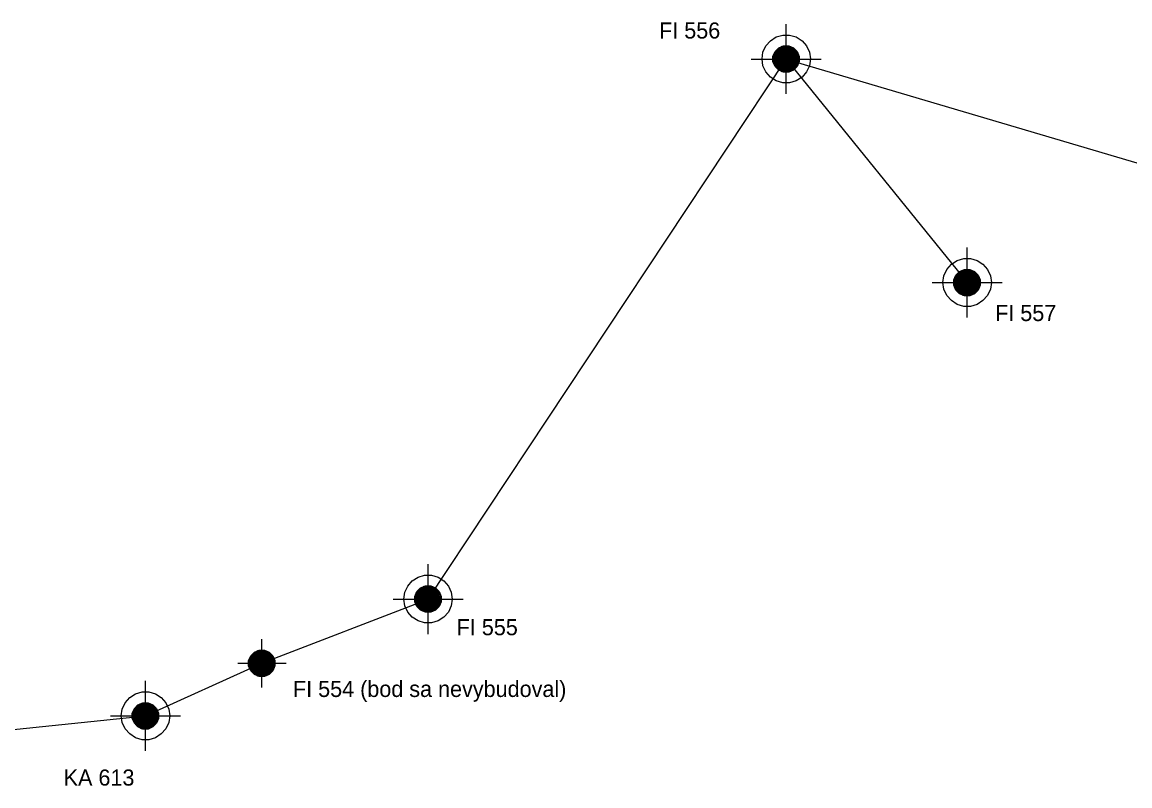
# Model space of a CAD drawing. Extents: x -346533 to -339969, y -1273090 to -1271585.
# Drawn here: x -340999 to -340484, y -1271944 to -1271589 of the extents above; entities that cross this region are included whole.
import ezdxf

# ---------------------------------------------------------------- set-up
doc = ezdxf.new("R2010")
doc.units = 0
for name, color, linetype in [('BP_11', 7, 'Continuous'), ('BP_12', 7, 'Continuous'), ('BP_14', 7, 'Continuous')]:
    doc.layers.add(name, color=color, linetype=linetype)

msp = doc.modelspace()

# ---------------------------------------------------------------- linework, layer by layer
at = {"layer": 'BP_11'}
for points in [[(-340643.57, -1271622.32), (-340643.57, -1271615.97), (-340643.57, -1271609.62), (-340643.57, -1271603.27), (-340643.57, -1271596.92), (-340643.57, -1271590.57), (-340643.57, -1271589.82)], [(-340643.57, -1271599.92), (-340642.37, -1271599.92), (-340640.12, -1271600.87), (-340638.42, -1271602.57), (-340637.47, -1271604.82), (-340637.47, -1271607.27), (-340638.42, -1271609.52), (-340640.12, -1271611.22), (-340642.37, -1271612.17), (-340644.82, -1271612.17), (-340647.07, -1271611.22), (-340648.77, -1271609.52), (-340649.72, -1271607.27), (-340649.72, -1271604.82), (-340648.77, -1271602.57), (-340647.07, -1271600.87), (-340644.82, -1271599.92), (-340643.62, -1271599.92), (-340641.82, -1271600.27), (-340645.42, -1271600.27), (-340646.22, -1271600.67), (-340641.02, -1271600.67), (-340640.22, -1271601.07), (-340646.57, -1271601.07), (-340647.02, -1271601.07), (-340647.42, -1271601.47), (-340641.07, -1271601.47), (-340639.82, -1271601.47), (-340639.42, -1271601.87), (-340645.77, -1271601.87), (-340647.82, -1271601.87), (-340648.22, -1271602.27), (-340641.87, -1271602.27), (-340639.02, -1271602.27), (-340638.62, -1271602.67), (-340644.97, -1271602.67), (-340648.62, -1271602.67), (-340648.62, -1271603.07), (-340642.27, -1271603.07), (-340638.62, -1271603.07), (-340638.22, -1271603.47), (-340644.57, -1271603.47), (-340649.02, -1271603.47), (-340649.02, -1271603.87), (-340642.67, -1271603.87), (-340638.22, -1271603.87), (-340638.22, -1271604.27), (-340644.57, -1271604.27), (-340649.02, -1271604.27), (-340649.42, -1271604.67), (-340643.07, -1271604.67), (-340637.82, -1271604.67), (-340637.82, -1271605.07), (-340644.17, -1271605.07), (-340649.42, -1271605.07), (-340649.42, -1271605.47), (-340643.07, -1271605.47), (-340637.82, -1271605.47), (-340637.82, -1271605.87), (-340644.17, -1271605.87), (-340649.42, -1271605.87), (-340649.42, -1271606.27), (-340643.07, -1271606.27), (-340637.82, -1271606.27), (-340637.82, -1271606.67), (-340644.17, -1271606.67), (-340649.42, -1271606.67), (-340649.42, -1271607.07), (-340643.07, -1271607.07), (-340637.82, -1271607.07), (-340637.82, -1271607.47), (-340644.17, -1271607.47), (-340649.42, -1271607.47), (-340649.42, -1271607.87), (-340643.07, -1271607.87), (-340637.82, -1271607.87), (-340638.22, -1271608.27), (-340644.57, -1271608.27), (-340649.02, -1271608.27), (-340649.02, -1271608.67), (-340642.67, -1271608.67), (-340638.22, -1271608.67), (-340638.62, -1271609.07), (-340644.97, -1271609.07), (-340648.62, -1271609.07), (-340648.62, -1271609.47), (-340642.27, -1271609.47), (-340638.62, -1271609.47), (-340639.02, -1271609.87), (-340645.37, -1271609.87), (-340648.22, -1271609.87), (-340647.82, -1271610.27), (-340641.47, -1271610.27), (-340639.42, -1271610.27), (-340639.82, -1271610.67), (-340646.17, -1271610.67), (-340647.42, -1271610.67), (-340647.02, -1271611.07), (-340640.67, -1271611.07), (-340640.22, -1271611.07)], [(-340659.82, -1271606.07), (-340653.47, -1271606.07), (-340647.12, -1271606.07), (-340640.77, -1271606.07), (-340634.42, -1271606.07), (-340628.07, -1271606.07), (-340627.32, -1271606.07)], [(-340640.22, -1271611.07), (-340641.02, -1271611.47), (-340646.22, -1271611.47), (-340645.42, -1271611.87), (-340641.82, -1271611.87)], [(-340559.43, -1271726.28), (-340559.43, -1271719.93), (-340559.43, -1271713.58), (-340559.43, -1271707.23), (-340559.43, -1271700.88), (-340559.43, -1271694.53), (-340559.43, -1271693.78)], [(-340559.43, -1271703.88), (-340558.23, -1271703.88), (-340555.98, -1271704.83), (-340554.28, -1271706.53), (-340553.33, -1271708.78), (-340553.33, -1271711.23), (-340554.28, -1271713.48), (-340555.98, -1271715.18), (-340558.23, -1271716.13), (-340560.68, -1271716.13), (-340562.93, -1271715.18), (-340564.63, -1271713.48), (-340565.58, -1271711.23), (-340565.58, -1271708.78), (-340564.63, -1271706.53), (-340562.93, -1271704.83), (-340560.68, -1271703.88), (-340559.48, -1271703.88), (-340557.68, -1271704.23), (-340561.28, -1271704.23), (-340562.08, -1271704.63), (-340556.88, -1271704.63), (-340556.08, -1271705.03), (-340562.43, -1271705.03), (-340562.88, -1271705.03), (-340563.28, -1271705.43), (-340556.93, -1271705.43), (-340555.68, -1271705.43), (-340555.28, -1271705.83), (-340561.63, -1271705.83), (-340563.68, -1271705.83), (-340564.08, -1271706.23), (-340557.73, -1271706.23), (-340554.88, -1271706.23), (-340554.48, -1271706.63), (-340560.83, -1271706.63), (-340564.48, -1271706.63), (-340564.48, -1271707.03), (-340558.13, -1271707.03), (-340554.48, -1271707.03), (-340554.08, -1271707.43), (-340560.43, -1271707.43), (-340564.88, -1271707.43), (-340564.88, -1271707.83), (-340558.53, -1271707.83), (-340554.08, -1271707.83), (-340554.08, -1271708.23), (-340560.43, -1271708.23), (-340564.88, -1271708.23), (-340565.28, -1271708.63), (-340558.93, -1271708.63), (-340553.68, -1271708.63), (-340553.68, -1271709.03), (-340560.03, -1271709.03), (-340565.28, -1271709.03), (-340565.28, -1271709.43), (-340558.93, -1271709.43), (-340553.68, -1271709.43), (-340553.68, -1271709.83), (-340560.03, -1271709.83), (-340565.28, -1271709.83), (-340565.28, -1271710.23), (-340558.93, -1271710.23), (-340553.68, -1271710.23), (-340553.68, -1271710.63), (-340560.03, -1271710.63), (-340565.28, -1271710.63), (-340565.28, -1271711.03), (-340558.93, -1271711.03), (-340553.68, -1271711.03), (-340553.68, -1271711.43), (-340560.03, -1271711.43), (-340565.28, -1271711.43), (-340565.28, -1271711.83), (-340558.93, -1271711.83), (-340553.68, -1271711.83), (-340554.08, -1271712.23), (-340560.43, -1271712.23), (-340564.88, -1271712.23), (-340564.88, -1271712.63), (-340558.53, -1271712.63), (-340554.08, -1271712.63), (-340554.48, -1271713.03), (-340560.83, -1271713.03), (-340564.48, -1271713.03), (-340564.48, -1271713.43), (-340558.13, -1271713.43), (-340554.48, -1271713.43), (-340554.88, -1271713.83), (-340561.23, -1271713.83), (-340564.08, -1271713.83), (-340563.68, -1271714.23), (-340557.33, -1271714.23), (-340555.28, -1271714.23), (-340555.68, -1271714.63), (-340562.03, -1271714.63), (-340563.28, -1271714.63), (-340562.88, -1271715.03), (-340556.53, -1271715.03), (-340556.08, -1271715.03)], [(-340575.68, -1271710.03), (-340569.33, -1271710.03), (-340562.98, -1271710.03), (-340556.63, -1271710.03), (-340550.28, -1271710.03), (-340543.93, -1271710.03), (-340543.18, -1271710.03)], [(-340556.08, -1271715.03), (-340556.88, -1271715.43), (-340562.08, -1271715.43), (-340561.28, -1271715.83), (-340557.68, -1271715.83)], [(-340810.08, -1271873.47), (-340810.08, -1271867.12), (-340810.08, -1271860.77), (-340810.08, -1271854.42), (-340810.08, -1271848.07), (-340810.08, -1271841.72), (-340810.08, -1271840.97)], [(-340810.08, -1271851.07), (-340808.88, -1271851.07), (-340806.63, -1271852.02), (-340804.93, -1271853.72), (-340803.98, -1271855.97), (-340803.98, -1271858.42), (-340804.93, -1271860.67), (-340806.63, -1271862.37), (-340808.88, -1271863.32), (-340811.33, -1271863.32), (-340813.58, -1271862.37), (-340815.28, -1271860.67), (-340816.23, -1271858.42), (-340816.23, -1271855.97), (-340815.28, -1271853.72), (-340813.58, -1271852.02), (-340811.33, -1271851.07), (-340810.13, -1271851.07), (-340808.33, -1271851.42), (-340811.93, -1271851.42), (-340812.73, -1271851.82), (-340807.53, -1271851.82), (-340806.73, -1271852.22), (-340813.08, -1271852.22), (-340813.53, -1271852.22), (-340813.93, -1271852.62), (-340807.58, -1271852.62), (-340806.33, -1271852.62), (-340805.93, -1271853.02), (-340812.28, -1271853.02), (-340814.33, -1271853.02), (-340814.73, -1271853.42), (-340808.38, -1271853.42), (-340805.53, -1271853.42), (-340805.13, -1271853.82), (-340811.48, -1271853.82), (-340815.13, -1271853.82), (-340815.13, -1271854.22), (-340808.78, -1271854.22), (-340805.13, -1271854.22), (-340804.73, -1271854.62), (-340811.08, -1271854.62), (-340815.53, -1271854.62), (-340815.53, -1271855.02), (-340809.18, -1271855.02), (-340804.73, -1271855.02), (-340804.73, -1271855.42), (-340811.08, -1271855.42), (-340815.53, -1271855.42), (-340815.93, -1271855.82), (-340809.58, -1271855.82), (-340804.33, -1271855.82), (-340804.33, -1271856.22), (-340810.68, -1271856.22), (-340815.93, -1271856.22), (-340815.93, -1271856.62), (-340809.58, -1271856.62), (-340804.33, -1271856.62), (-340804.33, -1271857.02), (-340810.68, -1271857.02), (-340815.93, -1271857.02), (-340815.93, -1271857.42), (-340809.58, -1271857.42), (-340804.33, -1271857.42), (-340804.33, -1271857.82), (-340810.68, -1271857.82), (-340815.93, -1271857.82), (-340815.93, -1271858.22), (-340809.58, -1271858.22), (-340804.33, -1271858.22), (-340804.33, -1271858.62), (-340810.68, -1271858.62), (-340815.93, -1271858.62), (-340815.93, -1271859.02), (-340809.58, -1271859.02), (-340804.33, -1271859.02), (-340804.73, -1271859.42), (-340811.08, -1271859.42), (-340815.53, -1271859.42), (-340815.53, -1271859.82), (-340809.18, -1271859.82), (-340804.73, -1271859.82), (-340805.13, -1271860.22), (-340811.48, -1271860.22), (-340815.13, -1271860.22), (-340815.13, -1271860.62), (-340808.78, -1271860.62), (-340805.13, -1271860.62), (-340805.53, -1271861.02), (-340811.88, -1271861.02), (-340814.73, -1271861.02), (-340814.33, -1271861.42), (-340807.98, -1271861.42), (-340805.93, -1271861.42), (-340806.33, -1271861.82), (-340812.68, -1271861.82), (-340813.93, -1271861.82), (-340813.53, -1271862.22), (-340807.18, -1271862.22), (-340806.73, -1271862.22)], [(-340826.33, -1271857.22), (-340819.98, -1271857.22), (-340813.63, -1271857.22), (-340807.28, -1271857.22), (-340800.93, -1271857.22), (-340794.58, -1271857.22), (-340793.83, -1271857.22)], [(-340806.73, -1271862.22), (-340807.53, -1271862.62), (-340812.73, -1271862.62), (-340811.93, -1271863.02), (-340808.33, -1271863.02)], [(-340887.37, -1271898.31), (-340887.37, -1271891.96), (-340887.37, -1271885.61), (-340887.37, -1271879.26), (-340887.37, -1271875.81)], [(-340887.37, -1271880.91), (-340886.17, -1271880.91), (-340883.92, -1271881.86), (-340882.22, -1271883.56), (-340881.27, -1271885.81), (-340881.27, -1271888.26), (-340882.22, -1271890.51), (-340883.92, -1271892.21), (-340886.17, -1271893.16), (-340888.62, -1271893.16), (-340890.87, -1271892.21), (-340892.57, -1271890.51), (-340893.52, -1271888.26), (-340893.52, -1271885.81), (-340892.57, -1271883.56), (-340890.87, -1271881.86), (-340888.62, -1271880.91), (-340887.42, -1271880.91), (-340885.62, -1271881.26), (-340889.22, -1271881.26), (-340890.02, -1271881.66), (-340884.82, -1271881.66), (-340884.02, -1271882.06), (-340890.37, -1271882.06), (-340890.82, -1271882.06), (-340891.22, -1271882.46), (-340884.87, -1271882.46), (-340883.62, -1271882.46), (-340883.22, -1271882.86), (-340889.57, -1271882.86), (-340891.62, -1271882.86), (-340892.02, -1271883.26), (-340885.67, -1271883.26), (-340882.82, -1271883.26), (-340882.42, -1271883.66), (-340888.77, -1271883.66), (-340892.42, -1271883.66), (-340892.42, -1271884.06), (-340886.07, -1271884.06), (-340882.42, -1271884.06), (-340882.02, -1271884.46), (-340888.37, -1271884.46), (-340892.82, -1271884.46), (-340892.82, -1271884.86), (-340886.47, -1271884.86), (-340882.02, -1271884.86), (-340881.62, -1271885.26), (-340887.97, -1271885.26), (-340893.22, -1271885.26), (-340893.22, -1271885.66), (-340886.87, -1271885.66), (-340881.62, -1271885.66), (-340881.62, -1271886.06), (-340887.97, -1271886.06), (-340893.22, -1271886.06), (-340893.22, -1271886.46), (-340886.87, -1271886.46), (-340881.62, -1271886.46), (-340881.62, -1271886.86), (-340887.97, -1271886.86), (-340893.22, -1271886.86), (-340893.22, -1271887.26), (-340886.87, -1271887.26), (-340881.62, -1271887.26), (-340881.62, -1271887.66), (-340887.97, -1271887.66), (-340893.22, -1271887.66), (-340893.22, -1271888.06), (-340886.87, -1271888.06), (-340881.62, -1271888.06), (-340881.62, -1271888.46), (-340887.97, -1271888.46), (-340893.22, -1271888.46), (-340893.22, -1271888.86), (-340886.87, -1271888.86), (-340881.62, -1271888.86), (-340882.02, -1271889.26), (-340888.37, -1271889.26), (-340892.82, -1271889.26), (-340892.82, -1271889.66), (-340886.47, -1271889.66), (-340882.02, -1271889.66), (-340882.42, -1271890.06), (-340888.77, -1271890.06), (-340892.42, -1271890.06), (-340892.42, -1271890.46), (-340886.07, -1271890.46), (-340882.42, -1271890.46), (-340882.82, -1271890.86), (-340889.17, -1271890.86), (-340892.02, -1271890.86), (-340891.62, -1271891.26), (-340885.27, -1271891.26), (-340883.22, -1271891.26), (-340883.62, -1271891.66), (-340889.97, -1271891.66), (-340891.22, -1271891.66), (-340890.82, -1271892.06), (-340884.47, -1271892.06), (-340884.02, -1271892.06)], [(-340898.62, -1271887.06), (-340892.27, -1271887.06), (-340885.92, -1271887.06), (-340879.57, -1271887.06), (-340876.12, -1271887.06)], [(-340941.47, -1271927.77), (-340941.47, -1271921.42), (-340941.47, -1271915.07), (-340941.47, -1271908.72), (-340941.47, -1271902.37), (-340941.47, -1271896.02), (-340941.47, -1271895.27)], [(-340884.02, -1271892.06), (-340884.82, -1271892.46), (-340890.02, -1271892.46), (-340889.22, -1271892.86), (-340885.62, -1271892.86)], [(-340941.47, -1271905.37), (-340940.27, -1271905.37), (-340938.02, -1271906.32), (-340936.32, -1271908.02), (-340935.37, -1271910.27), (-340935.37, -1271912.72), (-340936.32, -1271914.97), (-340938.02, -1271916.67), (-340940.27, -1271917.62), (-340942.72, -1271917.62), (-340944.97, -1271916.67), (-340946.67, -1271914.97), (-340947.62, -1271912.72), (-340947.62, -1271910.27), (-340946.67, -1271908.02), (-340944.97, -1271906.32), (-340942.72, -1271905.37), (-340941.52, -1271905.37), (-340939.72, -1271905.72), (-340943.32, -1271905.72), (-340944.12, -1271906.12), (-340938.92, -1271906.12), (-340938.12, -1271906.52), (-340944.47, -1271906.52), (-340944.92, -1271906.52), (-340945.32, -1271906.92), (-340938.97, -1271906.92), (-340937.72, -1271906.92), (-340937.32, -1271907.32), (-340943.67, -1271907.32), (-340945.72, -1271907.32), (-340946.12, -1271907.72), (-340939.77, -1271907.72), (-340936.92, -1271907.72), (-340936.52, -1271908.12), (-340942.87, -1271908.12), (-340946.52, -1271908.12), (-340946.52, -1271908.52), (-340940.17, -1271908.52), (-340936.52, -1271908.52), (-340936.12, -1271908.92), (-340942.47, -1271908.92), (-340946.92, -1271908.92), (-340946.92, -1271909.32), (-340940.57, -1271909.32), (-340936.12, -1271909.32), (-340936.12, -1271909.72), (-340942.47, -1271909.72), (-340946.92, -1271909.72), (-340947.32, -1271910.12), (-340940.97, -1271910.12), (-340935.72, -1271910.12), (-340935.72, -1271910.52), (-340942.07, -1271910.52), (-340947.32, -1271910.52), (-340947.32, -1271910.92), (-340940.97, -1271910.92), (-340935.72, -1271910.92), (-340935.72, -1271911.32), (-340942.07, -1271911.32), (-340947.32, -1271911.32), (-340947.32, -1271911.72), (-340940.97, -1271911.72), (-340935.72, -1271911.72), (-340935.72, -1271912.12), (-340942.07, -1271912.12), (-340947.32, -1271912.12), (-340947.32, -1271912.52), (-340940.97, -1271912.52), (-340935.72, -1271912.52), (-340935.72, -1271912.92), (-340942.07, -1271912.92), (-340947.32, -1271912.92), (-340947.32, -1271913.32), (-340940.97, -1271913.32), (-340935.72, -1271913.32), (-340936.12, -1271913.72), (-340942.47, -1271913.72), (-340946.92, -1271913.72), (-340946.92, -1271914.12), (-340940.57, -1271914.12), (-340936.12, -1271914.12), (-340936.52, -1271914.52), (-340942.87, -1271914.52), (-340946.52, -1271914.52), (-340946.52, -1271914.92), (-340940.17, -1271914.92), (-340936.52, -1271914.92), (-340936.92, -1271915.32), (-340943.27, -1271915.32), (-340946.12, -1271915.32), (-340945.72, -1271915.72), (-340939.37, -1271915.72), (-340937.32, -1271915.72), (-340937.72, -1271916.12), (-340944.07, -1271916.12), (-340945.32, -1271916.12), (-340944.92, -1271916.52), (-340938.57, -1271916.52), (-340938.12, -1271916.52)], [(-340957.72, -1271911.52), (-340951.37, -1271911.52), (-340945.02, -1271911.52), (-340938.67, -1271911.52), (-340932.32, -1271911.52), (-340925.97, -1271911.52), (-340925.22, -1271911.52)], [(-340938.12, -1271916.52), (-340938.92, -1271916.92), (-340944.12, -1271916.92), (-340943.32, -1271917.32), (-340939.72, -1271917.32)]]:
    msp.add_lwpolyline(points, dxfattribs=at)
for points in [[(-340641.97, -1271594.92), (-340638.92, -1271595.82), (-340636.22, -1271597.57), (-340634.12, -1271599.97), (-340632.77, -1271602.87), (-340632.32, -1271606.02), (-340632.77, -1271609.17), (-340634.12, -1271612.07), (-340636.22, -1271614.47), (-340638.92, -1271616.22), (-340641.97, -1271617.12), (-340645.17, -1271617.12), (-340648.22, -1271616.22), (-340650.92, -1271614.47), (-340653.02, -1271612.07), (-340654.37, -1271609.17), (-340654.82, -1271606.02), (-340654.37, -1271602.87), (-340653.02, -1271599.97), (-340650.92, -1271597.57), (-340648.22, -1271595.82), (-340645.17, -1271594.92)], [(-340557.83, -1271698.88), (-340554.78, -1271699.78), (-340552.08, -1271701.53), (-340549.98, -1271703.93), (-340548.63, -1271706.83), (-340548.18, -1271709.98), (-340548.63, -1271713.13), (-340549.98, -1271716.03), (-340552.08, -1271718.43), (-340554.78, -1271720.18), (-340557.83, -1271721.08), (-340561.03, -1271721.08), (-340564.08, -1271720.18), (-340566.78, -1271718.43), (-340568.88, -1271716.03), (-340570.23, -1271713.13), (-340570.68, -1271709.98), (-340570.23, -1271706.83), (-340568.88, -1271703.93), (-340566.78, -1271701.53), (-340564.08, -1271699.78), (-340561.03, -1271698.88)], [(-340808.48, -1271846.07), (-340805.43, -1271846.97), (-340802.73, -1271848.72), (-340800.63, -1271851.12), (-340799.28, -1271854.02), (-340798.83, -1271857.17), (-340799.28, -1271860.32), (-340800.63, -1271863.22), (-340802.73, -1271865.62), (-340805.43, -1271867.37), (-340808.48, -1271868.27), (-340811.68, -1271868.27), (-340814.73, -1271867.37), (-340817.43, -1271865.62), (-340819.53, -1271863.22), (-340820.88, -1271860.32), (-340821.33, -1271857.17), (-340820.88, -1271854.02), (-340819.53, -1271851.12), (-340817.43, -1271848.72), (-340814.73, -1271846.97), (-340811.68, -1271846.07)], [(-340886.17, -1271880.91), (-340883.92, -1271881.86), (-340882.22, -1271883.56), (-340881.27, -1271885.81), (-340881.27, -1271888.26), (-340882.22, -1271890.51), (-340883.92, -1271892.21), (-340886.17, -1271893.16), (-340888.62, -1271893.16), (-340890.87, -1271892.21), (-340892.57, -1271890.51), (-340893.52, -1271888.26), (-340893.52, -1271885.81), (-340892.57, -1271883.56), (-340890.87, -1271881.86), (-340888.62, -1271880.91)], [(-340939.87, -1271900.37), (-340936.82, -1271901.27), (-340934.12, -1271903.02), (-340932.02, -1271905.42), (-340930.67, -1271908.32), (-340930.22, -1271911.47), (-340930.67, -1271914.62), (-340932.02, -1271917.52), (-340934.12, -1271919.92), (-340936.82, -1271921.67), (-340939.87, -1271922.57), (-340943.07, -1271922.57), (-340946.12, -1271921.67), (-340948.82, -1271919.92), (-340950.92, -1271917.52), (-340952.27, -1271914.62), (-340952.72, -1271911.47), (-340952.27, -1271908.32), (-340950.92, -1271905.42), (-340948.82, -1271903.02), (-340946.12, -1271901.27), (-340943.07, -1271900.37)]]:
    msp.add_lwpolyline(points, close=True, dxfattribs=at)
at = {"layer": 'BP_14'}
for p, q in [((-340810.08, -1271857.22), (-340643.57, -1271606.07)), ((-340643.57, -1271606.07), (-340397.23, -1271679.02)), ((-340643.57, -1271606.07), (-340559.43, -1271710.03)), ((-340887.37, -1271887.06), (-340810.08, -1271857.22)), ((-340941.47, -1271911.52), (-340887.37, -1271887.06)), ((-341132.14, -1271931.34), (-340941.47, -1271911.52))]:
    msp.add_line(p, q, dxfattribs=at)

# ---------------------------------------------------------------- texts
at = {"layer": 'BP_12'}
for s, p in [('FI 556', (-340702.68, -1271596.54)), ('FI 557', (-340546.42, -1271727.92)), ('FI 555', (-340796.8, -1271874.01)), ('FI 554 (bod sa nevybudoval)', (-340872.9, -1271902.72)), ('KA 613', (-340979.53, -1271943.93))]:
    msp.add_text(s, height=7.5, dxfattribs=at).set_placement(p)

doc.saveas('drawing.dxf')
